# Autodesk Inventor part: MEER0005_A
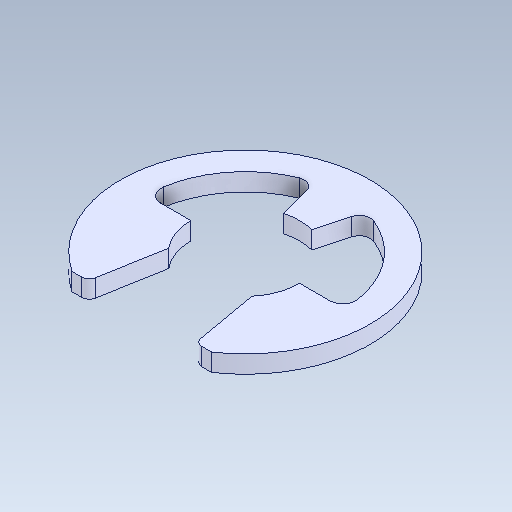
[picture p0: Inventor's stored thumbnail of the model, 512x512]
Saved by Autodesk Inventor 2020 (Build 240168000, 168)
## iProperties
Created: 2017-09
Part Number: MEER0005_A
Material: Générique
Document SubType Name: Modeling
Designer: bruno
Density: 1 g/cm^3
Appearance: Par défaut
Mass: 0.0163928 g
Surface Area: 0.815559 cm^2
Volume: 0.0163928 cm^3
Sending System: SolidWorks 2016
Author: bruno
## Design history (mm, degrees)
feature "Importée1"
node "Solide1"
